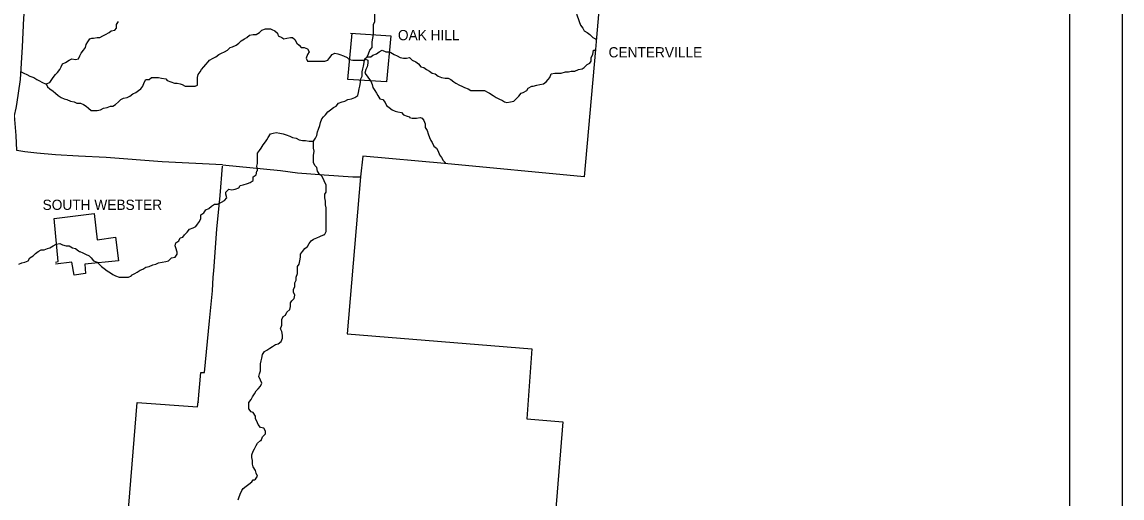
# Model space of a CAD drawing. Extents: x 0 to 34, y 0 to 22.
# Drawn here: x 6.907 to 9, y 16.352 to 17.259 of the extents above; entities that cross this region are included whole.
import ezdxf

# ---------------------------------------------------------------- set-up
doc = ezdxf.new("R2010")
doc.units = 0
doc.layers.add('Default', color=7, linetype='Continuous')
doc.layers.add('SH_Data', color=7, linetype='Continuous')

msp = doc.modelspace()

# ---------------------------------------------------------------- linework, layer by layer
at = {"layer": 'Default'}
for points in [[(8.0841, 18.2916), (8.0814, 18.2535), (8.0691, 18.0939), (8.0391, 17.7013), (8.0173, 17.4272), (7.9996, 17.2295), (7.9982, 17.2064), (7.9764, 16.9637), (7.7105, 16.9896), (7.5551, 17.0032)], [(7.2879, 16.9868), (7.1733, 16.9923), (7.067, 17.0005), (7.0138, 17.0032), (6.9702, 17.0059), (6.9347, 17.0087), (6.9116, 17.0114), (6.8966, 17.0141), (6.8952, 17.0427), (6.8925, 17.0809), (6.8952, 17.0946), (6.8966, 17.1014), (6.9034, 17.1491), (6.9075, 17.2118), (6.9102, 17.2663), (6.9157, 17.3331), (6.9225, 17.419), (6.8175, 17.4272), (6.733, 17.4327)], [(7.941, 17.325), (7.9464, 17.3195), (7.9491, 17.3127), (7.9519, 17.3086), (7.9559, 17.3018), (7.9573, 17.2963), (7.9587, 17.2909), (7.96, 17.2841), (7.9614, 17.2772), (7.9628, 17.2704), (7.9655, 17.2636), (7.9669, 17.2595), (7.9696, 17.2527), (7.9737, 17.2473), (7.9764, 17.2418), (7.9819, 17.2391), (7.9873, 17.235), (7.9928, 17.2295), (7.9982, 17.2268), (7.9996, 17.2254)], [(7.5633, 17.1927), (7.566, 17.1982), (7.5687, 17.205), (7.5728, 17.2104), (7.5728, 17.2145), (7.5728, 17.2213), (7.5742, 17.2282), (7.5756, 17.235), (7.5756, 17.2418), (7.5756, 17.2473), (7.5756, 17.2541), (7.5783, 17.2595), (7.5783, 17.2677), (7.5783, 17.2745), (7.5783, 17.2759)], [(7.0425, 17.2282), (7.0493, 17.2295), (7.0547, 17.2295), (7.0602, 17.2323), (7.0656, 17.235), (7.0725, 17.2391), (7.0765, 17.2418), (7.0834, 17.2432), (7.0861, 17.2473), (7.0861, 17.2541), (7.0902, 17.2595)], [(7.2483, 17.1682), (7.2524, 17.1736), (7.2565, 17.1777), (7.2606, 17.1832), (7.2633, 17.1859), (7.2701, 17.19), (7.2756, 17.1927), (7.2811, 17.1968), (7.2865, 17.1995), (7.292, 17.2023), (7.2974, 17.205), (7.3029, 17.2104), (7.307, 17.2118), (7.3138, 17.2145), (7.3192, 17.2186), (7.3233, 17.2227), (7.3301, 17.2268), (7.3342, 17.2295), (7.3397, 17.2336), (7.3465, 17.235), (7.352, 17.235), (7.3588, 17.2391), (7.3629, 17.2432), (7.3697, 17.2459), (7.3765, 17.2459), (7.3792, 17.2459), (7.3819, 17.2445)], [(7.3819, 17.2445), (7.3874, 17.2418), (7.3929, 17.2377), (7.3942, 17.2323), (7.401, 17.2295), (7.4051, 17.2268), (7.4106, 17.2282), (7.4174, 17.2295), (7.4215, 17.2295), (7.4256, 17.2254), (7.4297, 17.2186), (7.4338, 17.2145), (7.4378, 17.2104), (7.4433, 17.2104), (7.4501, 17.2077), (7.4528, 17.2023), (7.4501, 17.1968), (7.4474, 17.19), (7.4501, 17.1845), (7.4501, 17.1845), (7.4501, 17.1845)], [(7.5319, 17.2377), (7.6083, 17.2323), (7.6001, 17.145), (7.5265, 17.1491), (7.5347, 17.2377)], [(6.9525, 17.1409), (6.9593, 17.1436), (6.962, 17.1477), (6.9661, 17.1532), (6.9702, 17.1586), (6.9743, 17.1627), (6.9784, 17.1682), (6.9811, 17.1736), (6.9838, 17.1791), (6.9893, 17.1818), (6.9961, 17.1859), (7.0016, 17.1886), (7.0084, 17.1873), (7.0138, 17.1886), (7.0166, 17.1941), (7.0193, 17.1995), (7.0234, 17.205), (7.0275, 17.2104), (7.0288, 17.2159), (7.0315, 17.2213), (7.0356, 17.2268), (7.0397, 17.2282), (7.0425, 17.2282)], [(7.4501, 17.1845), (7.4569, 17.1845), (7.4624, 17.1845), (7.4692, 17.1845), (7.4774, 17.1845), (7.4828, 17.1845), (7.4883, 17.1859), (7.4924, 17.1914), (7.4965, 17.1968), (7.5019, 17.1995), (7.5074, 17.1982), (7.5115, 17.1968), (7.5183, 17.1941), (7.5251, 17.1914), (7.5292, 17.1873), (7.536, 17.1859), (7.5428, 17.1859), (7.5496, 17.1859), (7.5565, 17.1859), (7.5592, 17.1859)], [(7.5592, 17.1886), (7.5633, 17.1927)], [(7.5592, 17.1859), (7.5592, 17.1873), (7.5592, 17.1886)], [(7.5592, 17.1859), (7.5592, 17.1873), (7.5592, 17.1886)], [(7.5592, 17.1886), (7.5646, 17.1859), (7.5646, 17.1804), (7.5633, 17.1736), (7.5606, 17.1682), (7.5592, 17.1614), (7.5633, 17.1559), (7.566, 17.1518), (7.5701, 17.1464), (7.5728, 17.1395), (7.5742, 17.1341), (7.5783, 17.1286), (7.581, 17.1232), (7.5837, 17.1191), (7.5878, 17.1123), (7.5933, 17.1109), (7.5974, 17.1055), (7.6001, 17.1), (7.6055, 17.0959), (7.611, 17.0918), (7.6165, 17.0891), (7.6219, 17.0877), (7.6287, 17.0864), (7.6328, 17.0823), (7.6396, 17.0796), (7.6437, 17.0782), (7.6437, 17.0782), (7.6437, 17.0768)], [(7.5633, 17.1927), (7.5701, 17.1927), (7.5742, 17.1954), (7.581, 17.1982), (7.5865, 17.2023), (7.5919, 17.205), (7.5987, 17.2023), (7.6055, 17.2023), (7.6083, 17.2009), (7.6151, 17.1968), (7.6205, 17.1941), (7.626, 17.1914), (7.6328, 17.19), (7.6383, 17.19), (7.6437, 17.1914), (7.6492, 17.1859), (7.656, 17.1832), (7.6614, 17.1791), (7.6655, 17.1736), (7.671, 17.1723), (7.6764, 17.1682), (7.6819, 17.1654), (7.6874, 17.1614), (7.6928, 17.16), (7.6983, 17.1559), (7.7051, 17.1532), (7.7119, 17.1518), (7.7174, 17.1518), (7.7228, 17.1491), (7.7283, 17.145), (7.7323, 17.1423), (7.7392, 17.1382), (7.7433, 17.1368)], [(7.8796, 17.1368), (7.8864, 17.1382), (7.8919, 17.1395), (7.8987, 17.1409), (7.9041, 17.145), (7.9082, 17.1491), (7.911, 17.1532), (7.9137, 17.16), (7.9205, 17.1614), (7.9273, 17.1614), (7.9328, 17.1614), (7.941, 17.1641), (7.9464, 17.1641), (7.9519, 17.1654), (7.9587, 17.1654), (7.9655, 17.1682), (7.9723, 17.1695), (7.9764, 17.1723), (7.9819, 17.1777), (7.9873, 17.1804), (7.99, 17.1845), (7.99, 17.1914), (7.9928, 17.1968), (7.9941, 17.205), (7.9982, 17.205), (7.9982, 17.2064)], [(7.2115, 17.1395), (7.217, 17.1368), (7.2238, 17.1368), (7.2292, 17.1368), (7.2361, 17.1368), (7.2402, 17.1382), (7.2402, 17.145), (7.2402, 17.1532), (7.2415, 17.1586), (7.2456, 17.1641), (7.2483, 17.1682), (7.2483, 17.1682)], [(7.461, 17.0318), (7.4651, 17.0373), (7.4678, 17.0427), (7.4692, 17.0496), (7.4706, 17.055), (7.4733, 17.0618), (7.4747, 17.0673), (7.4774, 17.0741), (7.4801, 17.0782), (7.4842, 17.0823), (7.4883, 17.0877), (7.4937, 17.0918), (7.4992, 17.0959), (7.5047, 17.0986), (7.5087, 17.1041), (7.5156, 17.1068), (7.521, 17.1082), (7.5265, 17.1109), (7.5333, 17.1123), (7.5401, 17.115), (7.5456, 17.1191), (7.5469, 17.1245), (7.5483, 17.1314), (7.5496, 17.1368), (7.551, 17.1436), (7.551, 17.1491), (7.5537, 17.1559), (7.5537, 17.1641), (7.5551, 17.1695), (7.5565, 17.175), (7.5578, 17.1818), (7.5578, 17.1845), (7.5592, 17.1859)], [(6.9048, 17.1641), (6.9102, 17.1614), (6.9157, 17.1586), (6.9211, 17.1559), (6.9293, 17.1532), (6.9347, 17.1491), (6.9388, 17.1477), (6.9457, 17.1436), (6.9511, 17.1409), (6.9525, 17.1409), (6.9525, 17.1409)], [(7.0847, 17.1014), (7.0902, 17.1068), (7.0943, 17.1109), (7.0997, 17.1136), (7.1065, 17.115), (7.112, 17.1177), (7.1174, 17.1218), (7.1229, 17.1245), (7.1284, 17.1286), (7.1324, 17.1314), (7.1365, 17.1368), (7.1393, 17.1436), (7.142, 17.1491), (7.1488, 17.1491), (7.1529, 17.1532), (7.1529, 17.1532)], [(7.1529, 17.1532), (7.1583, 17.1532), (7.1665, 17.1532), (7.172, 17.1518), (7.1802, 17.1505), (7.1829, 17.1477), (7.1897, 17.145), (7.1965, 17.1423), (7.202, 17.1423), (7.2074, 17.1409), (7.2115, 17.1395), (7.2115, 17.1395)], [(6.9525, 17.1409), (6.9552, 17.1355), (6.9593, 17.1314), (6.9661, 17.1273), (6.9702, 17.1232), (6.9756, 17.1191), (6.9811, 17.115), (6.9866, 17.1123), (6.992, 17.1109), (6.9988, 17.1082), (7.0056, 17.1068), (7.0111, 17.1041), (7.0179, 17.1041), (7.0234, 17.1014), (7.0288, 17.0986), (7.0329, 17.0946), (7.0384, 17.0905), (7.0438, 17.0905), (7.0493, 17.0905), (7.0561, 17.0918), (7.0615, 17.0946), (7.0684, 17.0959), (7.0752, 17.0986), (7.0793, 17.0986), (7.0847, 17.1014), (7.0847, 17.1014)], [(7.7433, 17.1368), (7.7487, 17.1341), (7.7555, 17.1314), (7.761, 17.1286), (7.7678, 17.1286), (7.7746, 17.1286), (7.7801, 17.1286), (7.7869, 17.1286), (7.7937, 17.1245), (7.7964, 17.1232), (7.8032, 17.1191), (7.8087, 17.115), (7.8142, 17.1123), (7.821, 17.1095), (7.8251, 17.1068), (7.8292, 17.1055), (7.836, 17.1068), (7.8428, 17.1082), (7.8469, 17.1123), (7.8523, 17.1177), (7.8564, 17.1232), (7.8605, 17.1245), (7.8673, 17.1286), (7.8701, 17.1327), (7.8769, 17.1368), (7.8782, 17.1368), (7.8796, 17.1368)], [(7.6437, 17.0768), (7.6492, 17.0755), (7.6574, 17.0755), (7.6642, 17.0768), (7.6683, 17.0755), (7.671, 17.0714), (7.6737, 17.0646), (7.6737, 17.0577), (7.6778, 17.0523), (7.6792, 17.0455), (7.6819, 17.0387), (7.6846, 17.0332), (7.6874, 17.0291), (7.6901, 17.0223), (7.6955, 17.0182), (7.6983, 17.0127), (7.701, 17.0059), (7.7051, 17.0005), (7.7078, 16.995), (7.7119, 16.9909), (7.7119, 16.9896)], [(7.3547, 16.9773), (7.3533, 16.9841), (7.3547, 16.9896), (7.3547, 16.995), (7.3547, 17.0005), (7.3547, 17.0087), (7.3588, 17.0141), (7.3615, 17.0182), (7.3656, 17.025), (7.3697, 17.0305), (7.3724, 17.0346), (7.3751, 17.0387), (7.3792, 17.0455), (7.3847, 17.0468), (7.3901, 17.0482), (7.3969, 17.0468), (7.4038, 17.0455), (7.4092, 17.0441), (7.416, 17.0414), (7.4215, 17.0387), (7.4283, 17.0373), (7.4338, 17.0346), (7.4406, 17.0332), (7.446, 17.0332), (7.4528, 17.0318), (7.4583, 17.0318), (7.4597, 17.0318), (7.461, 17.0318)], [(7.4733, 16.9678), (7.4692, 16.9746), (7.4678, 16.9814), (7.4638, 16.9855), (7.461, 16.9909), (7.461, 16.9977), (7.461, 17.0046), (7.4624, 17.0127), (7.461, 17.0182), (7.461, 17.025), (7.461, 17.0305), (7.461, 17.0318)], [(7.5551, 17.0032), (7.551, 16.9637)], [(7.2415, 16.5342), (7.247, 16.5914), (7.2538, 16.5914), (7.2633, 16.6896), (7.2688, 16.7469), (7.2701, 16.7728), (7.2715, 16.7851), (7.277, 16.8641), (7.2838, 16.9282), (7.2879, 16.9841), (7.2879, 16.9841), (7.2879, 16.9841)], [(7.2879, 16.9868), (7.3983, 16.9759), (7.431, 16.9718), (7.4815, 16.9678), (7.536, 16.9637), (7.551, 16.9637), (7.551, 16.9637)], [(7.2811, 16.9132), (7.2865, 16.9159), (7.292, 16.9187), (7.2961, 16.9241), (7.2947, 16.9309), (7.2947, 16.935), (7.3001, 16.9405), (7.3056, 16.9391), (7.3124, 16.9405), (7.3192, 16.9432), (7.322, 16.9473), (7.3274, 16.9487), (7.3356, 16.9514), (7.341, 16.9528), (7.3465, 16.9568), (7.3465, 16.9637), (7.352, 16.9678), (7.3533, 16.9746), (7.3547, 16.9759), (7.3547, 16.9773)], [(7.4828, 16.8546), (7.4856, 16.86), (7.4856, 16.8669), (7.4856, 16.8737), (7.4856, 16.8791), (7.4856, 16.8859), (7.4856, 16.8914), (7.4856, 16.8982), (7.4856, 16.905), (7.4842, 16.9105), (7.4842, 16.9173), (7.4828, 16.9241), (7.4828, 16.9309), (7.4856, 16.935), (7.4856, 16.9432), (7.4856, 16.9487), (7.4828, 16.9528), (7.4801, 16.9596), (7.4774, 16.965), (7.4747, 16.9678), (7.4733, 16.9678)], [(7.551, 16.9637), (7.5251, 16.6651), (7.8769, 16.6364), (7.8673, 16.5028), (7.9355, 16.4974), (7.9219, 16.3242), (7.915, 16.2288), (8.2464, 16.2083), (8.2845, 16.2042), (8.3336, 16.2015)], [(7.2129, 16.8491), (7.2156, 16.8532), (7.2211, 16.8587), (7.2252, 16.8641), (7.232, 16.8669), (7.2374, 16.8696), (7.2402, 16.8737), (7.2442, 16.8791), (7.247, 16.8846), (7.247, 16.8914), (7.2524, 16.8955), (7.2565, 16.9009), (7.262, 16.9037), (7.2674, 16.9078), (7.2729, 16.9119), (7.2783, 16.9119), (7.2811, 16.9132)], [(6.9702, 16.8014), (6.9756, 16.8028), (6.9675, 16.8846), (7.0438, 16.8941), (7.0493, 16.8437), (7.0847, 16.8491), (7.0902, 16.8041), (7.0261, 16.7973), (7.0275, 16.7796), (7.0056, 16.7769), (7.0016, 16.8014), (6.9702, 16.7973)], [(7.4079, 16.7005), (7.4106, 16.706), (7.416, 16.7114), (7.4174, 16.7169), (7.4174, 16.7237), (7.4201, 16.7278), (7.4242, 16.7319), (7.4256, 16.7387), (7.4229, 16.7442), (7.4229, 16.7496), (7.4256, 16.7551), (7.4256, 16.7619), (7.4283, 16.7673), (7.4283, 16.7728), (7.431, 16.7796), (7.431, 16.7864), (7.431, 16.7932), (7.4338, 16.7973), (7.4351, 16.8041), (7.4365, 16.811), (7.4365, 16.8164), (7.4406, 16.8219), (7.4447, 16.8273), (7.4501, 16.8314), (7.4528, 16.8369), (7.4569, 16.8423), (7.461, 16.845), (7.4678, 16.8478), (7.4733, 16.8505), (7.4801, 16.8532), (7.4815, 16.8532), (7.4828, 16.8546)], [(6.9007, 16.7973), (6.9061, 16.8001), (6.9116, 16.8014), (6.9184, 16.8041), (6.9211, 16.8096), (6.9279, 16.8137), (6.932, 16.8178), (6.9375, 16.8219), (6.9429, 16.8246), (6.9484, 16.8246), (6.9552, 16.8273), (6.9593, 16.8287), (6.9661, 16.8328), (6.9716, 16.8355), (6.9784, 16.8369), (6.9838, 16.8341), (6.9906, 16.8328), (6.9961, 16.8328), (7.0029, 16.8287), (7.0084, 16.8273), (7.0138, 16.8232), (7.0152, 16.8219), (7.0166, 16.8219)], [(7.1147, 16.7769), (7.1215, 16.7796), (7.1256, 16.7823), (7.1311, 16.7864), (7.1365, 16.7878), (7.142, 16.7919), (7.1488, 16.7932), (7.1556, 16.796), (7.1611, 16.7973), (7.1665, 16.8001), (7.1733, 16.8014), (7.1802, 16.8028), (7.1856, 16.8041), (7.1911, 16.8096), (7.1979, 16.811), (7.202, 16.8164), (7.202, 16.8205), (7.1993, 16.8287), (7.1979, 16.8328), (7.1993, 16.8382), (7.2047, 16.8423), (7.2074, 16.8478), (7.2129, 16.8491)], [(7.0166, 16.8219), (7.022, 16.8191), (7.0275, 16.8164), (7.0343, 16.8137), (7.0384, 16.8096), (7.0425, 16.8041), (7.0493, 16.8014), (7.0534, 16.7973), (7.0575, 16.7932), (7.0629, 16.7891), (7.0684, 16.7851), (7.0752, 16.781), (7.0793, 16.7782), (7.0847, 16.7755), (7.0915, 16.7728), (7.0984, 16.7728), (7.1038, 16.7728), (7.1093, 16.7728), (7.1147, 16.7755), (7.1147, 16.7769)], [(7.356, 16.5601), (7.3601, 16.5655), (7.3629, 16.571), (7.3601, 16.5765), (7.3574, 16.5833), (7.3588, 16.5887), (7.3601, 16.5942), (7.3601, 16.5996), (7.3601, 16.6078), (7.3615, 16.6133), (7.3629, 16.6187), (7.3642, 16.6255), (7.3683, 16.631), (7.3724, 16.6337), (7.3779, 16.6378), (7.3833, 16.6405), (7.3888, 16.6446), (7.3942, 16.646), (7.3997, 16.6501), (7.4024, 16.6569), (7.4024, 16.6623), (7.401, 16.6692), (7.3983, 16.6746), (7.401, 16.6814), (7.401, 16.6869), (7.401, 16.6923), (7.4038, 16.6978), (7.4079, 16.7005)], [(7.3615, 16.4619), (7.3642, 16.4687), (7.3697, 16.4742), (7.3697, 16.4796), (7.367, 16.4851), (7.3601, 16.4865), (7.356, 16.4919), (7.3533, 16.4987), (7.3506, 16.5028), (7.3506, 16.5083), (7.3465, 16.5151), (7.3424, 16.5165), (7.3383, 16.5219), (7.3383, 16.5274), (7.3383, 16.5342), (7.3424, 16.5396), (7.3451, 16.5451), (7.3492, 16.5505), (7.352, 16.556), (7.3547, 16.5587), (7.356, 16.5601)], [(7.1038, 16.2683), (7.1256, 16.5342)], [(7.1256, 16.5342), (7.2402, 16.526)], [(7.2402, 16.526), (7.2415, 16.5355), (7.2415, 16.5342)], [(7.3506, 16.3883), (7.3547, 16.3938), (7.352, 16.3992), (7.3506, 16.4047), (7.3465, 16.4115), (7.3451, 16.4169), (7.3451, 16.4237), (7.3438, 16.4292), (7.3438, 16.4347), (7.3465, 16.4415), (7.3492, 16.4456), (7.352, 16.4524), (7.3547, 16.4565), (7.3601, 16.4619), (7.3615, 16.4619)], [(7.3179, 16.3488), (7.3192, 16.3528), (7.322, 16.3597), (7.3247, 16.3665), (7.3274, 16.3706), (7.3329, 16.3747), (7.3383, 16.3788), (7.3438, 16.3828), (7.3465, 16.3869), (7.3492, 16.3869), (7.3506, 16.3883)]]:
    msp.add_lwpolyline(points, dxfattribs=at)
at = {"layer": 'SH_Data'}
for p, q in [((9, 21), (9, 14)), ((8.9, 20.9), (8.9, 14.1))]:
    msp.add_line(p, q, dxfattribs=at)

# ---------------------------------------------------------------- texts
at = {"layer": 'Default'}
for s, height, p in [('OAK HILL', 0.0195, (7.6219, 17.2241)), ('CENTERVILLE', 0.019502, (8.0228, 17.1914)), ('SOUTH WEBSTER', 0.019502, (6.9457, 16.9009))]:
    msp.add_text(s, height=height, dxfattribs=at).set_placement(p)

doc.saveas('drawing.dxf')
